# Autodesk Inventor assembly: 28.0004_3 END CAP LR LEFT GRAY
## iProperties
Created: 2007-04
Part Number: 28.0004_3 END CAP LR LEFT GRAY
Document SubType Name: Assembly
Designer: Andy Moles
Author: Andy Moles
